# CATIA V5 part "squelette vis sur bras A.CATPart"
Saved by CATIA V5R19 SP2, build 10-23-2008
Part number: squelette vis sur bras A
Bounding box of the stored display mesh (mm): x -100 to 100, y -100 to 50, z 0 to 0
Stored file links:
  G:\EU_thinkMotion\CFAO_2010\MMS_groupe3\MMS_groupe3\A reprendre\mmugnier\Systeme_Cric_Y\Systeme_Cric_Y\squelette vis sur bras A.CATPart
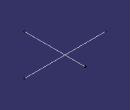
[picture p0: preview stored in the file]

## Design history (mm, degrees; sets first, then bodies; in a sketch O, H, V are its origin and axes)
Set1
  Line1 "Axe 3": type Normal, RefPoint {point type Coord, X 0, Y 0, Z 0}, RefSkin yz-plane, Start -100, End 100
  Line2 "Axe liaison helicoidale": type Normal, RefPoint {point type Coord, X 0, Y 0, Z 0}, RefSkin zx-plane, Start -50, End 100
Body1 (main body)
